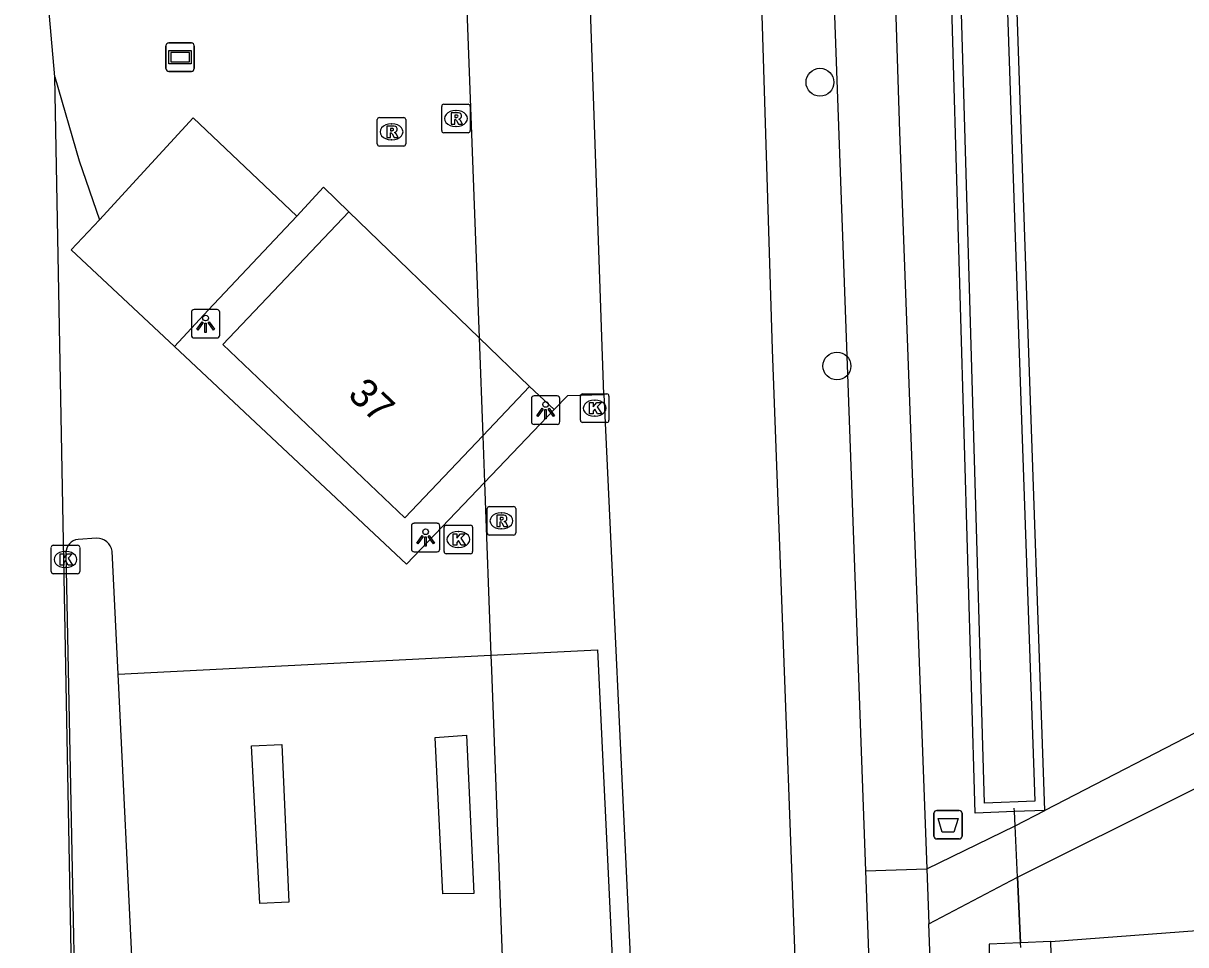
# Model space of a CAD drawing. Extents: x 162515 to 163909, y 388494 to 389773.
# Drawn here: x 162528.08 to 162568.87, y 388907.23 to 388939.56 of the extents above; entities that cross this region are included whole.
import ezdxf

# ---------------------------------------------------------------- set-up
doc = ezdxf.new("R2010")
doc.units = 0
for name, color, linetype in [('IMGEO_Afvalbak', 7, 'Continuous'), ('IMGEO_Berm_groen', 7, 'Continuous'), ('IMGEO_Boom', 7, 'Continuous'), ('IMGEO_Duiker', 7, 'Continuous'), ('IMGEO_Erf', 7, 'Continuous'), ('IMGEO_Grasland_overig', 7, 'Continuous'), ('IMGEO_Groenvoorziening', 7, 'Continuous'), ('IMGEO_Kolk', 7, 'Continuous'), ('IMGEO_Lichtpunt', 7, 'Continuous'), ('IMGEO_Loofbos', 7, 'Continuous'), ('IMGEO_Muur', 7, 'Continuous'), ('IMGEO_Pand', 7, 'Continuous'), ('IMGEO_Pand_nummerreeks', 7, 'Continuous'), ('IMGEO_Parkeervlak_open', 7, 'Continuous'), ('IMGEO_Reclamebord', 7, 'Continuous'), ('IMGEO_Rijbaan_lokaal_gesloten', 7, 'Continuous'), ('IMGEO_Rijbaan_lokaal_onverhard', 7, 'Continuous'), ('IMGEO_Rijbaan_lokaal_open', 7, 'Continuous'), ('IMGEO_Rijbaan_regionaal_gesloten', 7, 'Continuous'), ('IMGEO_Rioolput', 7, 'Continuous'), ('IMGEO_Voetpad_open', 7, 'Continuous'), ('IMGEO_Waterloop', 7, 'Continuous')]:
    doc.layers.add(name, color=color, linetype=linetype)

msp = doc.modelspace()

# ---------------------------------------------------------------- linework, layer by layer
at = {"layer": 'IMGEO_Afvalbak'}
for p, q in [((162560.036, 388911.045), (162560.036, 388911.845)), ((162560.036, 388911.845), (162560.036, 388911.045)), ((162560.136, 388911.945), (162560.926, 388911.945)), ((162560.926, 388911.945), (162560.136, 388911.945)), ((162561.026, 388911.845), (162561.026, 388911.045)), ((162561.026, 388911.045), (162561.026, 388911.845)), ((162560.926, 388910.945), (162560.136, 388910.945)), ((162560.136, 388910.945), (162560.926, 388910.945))]:
    msp.add_line(p, q, dxfattribs=at)
msp.add_lwpolyline([(162560.179, 388911.659), (162560.883, 388911.659), (162560.734, 388911.189), (162560.328, 388911.189), (162560.179, 388911.659)], dxfattribs=at)
for centre, start, end in [((162560.136, 388911.845), 90, 180), ((162560.136, 388911.845), 90, 180), ((162560.926, 388911.845), 0, 90), ((162560.926, 388911.845), 360, 90), ((162560.136, 388911.045), 180, 270), ((162560.136, 388911.045), 180, 270), ((162560.926, 388911.045), 270, 0), ((162560.926, 388911.045), 270, 0)]:
    msp.add_arc(centre, 0.1, start, end, dxfattribs=at)
at = {"layer": 'IMGEO_Berm_groen'}
msp.add_lwpolyline([(162563.923, 388911.946), (162562.861, 388911.906), (162561.484, 388911.855), (162559.805, 388969.627), (162558.753, 389000), (162555.964, 389080.524), (162557.523, 389080.69)], dxfattribs=at)
at = {"layer": 'IMGEO_Boom'}
for centre in [(162556.038, 388937.492), (162556.631, 388927.537)]:
    msp.add_circle(centre, 0.489, dxfattribs=at)
at = {"layer": 'IMGEO_Duiker'}
for points in [[(162543.608, 388941.114), (162543.637, 388940.341), (162544.076, 388928.528), (162544.204, 388925.086), (162544.265, 388923.449), (162544.49, 388917.392), (162544.51, 388916.869), (162544.884, 388906.812), (162544.893, 388906.576), (162545.214, 388897.949), (162545.319, 388895.129), (162545.332, 388894.768)], [(162563.083, 388907.137), (162563.075, 388907.302), (162562.968, 388909.608), (162562.884, 388911.41), (162562.861, 388911.906), (162562.853, 388912.022)]]:
    msp.add_lwpolyline(points, dxfattribs=at)
at = {"layer": 'IMGEO_Erf'}
msp.add_lwpolyline([(162563.923, 388911.946), (162563.311, 388929.674), (162561.923, 388970.136), (162560.632, 389000), (162557.523, 389080.69)], dxfattribs=at)
at = {"layer": 'IMGEO_Grasland_overig'}
for points in [[(162562.968, 388909.608), (162563.075, 388907.302)], [(162564.138, 388907.346), (162563.075, 388907.302)]]:
    msp.add_lwpolyline(points, dxfattribs=at)
at = {"layer": 'IMGEO_Groenvoorziening'}
msp.add_lwpolyline([(162563.075, 388907.302), (162561.978, 388907.257), (162562.125, 388898.48), (162562.164, 388896.116), (162562.928, 388869.681), (162566.625, 388758.14)], dxfattribs=at)
at = {"layer": 'IMGEO_Kolk'}
for p, q in [((162547.634, 388925.632), (162547.634, 388926.484)), ((162547.709, 388926.558), (162548.561, 388926.558)), ((162548.635, 388926.484), (162548.635, 388925.632)), ((162548.122, 388926.338), (162548.147, 388926.338)), ((162548.561, 388925.558), (162547.709, 388925.558)), ((162548.145, 388925.778), (162548.12, 388925.778)), ((162542.925, 388921.952), (162543.777, 388921.952)), ((162542.85, 388921.026), (162542.85, 388921.878)), ((162543.338, 388921.732), (162543.363, 388921.732)), ((162543.851, 388921.878), (162543.851, 388921.026)), ((162529.064, 388920.324), (162529.064, 388921.176)), ((162529.139, 388921.25), (162529.991, 388921.25)), ((162530.065, 388921.176), (162530.065, 388920.324)), ((162543.361, 388921.172), (162543.336, 388921.172)), ((162529.552, 388921.03), (162529.577, 388921.03)), ((162543.777, 388920.952), (162542.925, 388920.952)), ((162529.991, 388920.25), (162529.139, 388920.25)), ((162529.575, 388920.47), (162529.55, 388920.47))]:
    msp.add_line(p, q, dxfattribs=at)
for points in [[(162547.634, 388925.632), (162547.634, 388926.484)], [(162547.709, 388926.558), (162548.561, 388926.558)], [(162548.635, 388926.484), (162548.635, 388925.632)], [(162547.955, 388926.258), (162548.078, 388926.258), (162548.078, 388926.107), (162548.208, 388926.258), (162548.372, 388926.258), (162548.226, 388926.107), (162548.379, 388925.858), (162548.227, 388925.858), (162548.142, 388926.022), (162548.078, 388925.955), (162548.078, 388925.858), (162547.955, 388925.858), (162547.955, 388926.258)], [(162548.561, 388925.558), (162547.709, 388925.558)], [(162542.925, 388921.952), (162543.777, 388921.952)], [(162542.85, 388921.026), (162542.85, 388921.878)], [(162543.171, 388921.652), (162543.294, 388921.652), (162543.294, 388921.501), (162543.424, 388921.652), (162543.588, 388921.652), (162543.442, 388921.501), (162543.595, 388921.252), (162543.443, 388921.252), (162543.358, 388921.416), (162543.294, 388921.349), (162543.294, 388921.252), (162543.171, 388921.252), (162543.171, 388921.652)], [(162543.851, 388921.878), (162543.851, 388921.026)], [(162529.064, 388920.324), (162529.064, 388921.176)], [(162529.139, 388921.25), (162529.991, 388921.25)], [(162530.065, 388921.176), (162530.065, 388920.324)], [(162529.385, 388920.95), (162529.508, 388920.95), (162529.508, 388920.799), (162529.638, 388920.95), (162529.802, 388920.95), (162529.656, 388920.799), (162529.809, 388920.55), (162529.657, 388920.55), (162529.572, 388920.714), (162529.508, 388920.647), (162529.508, 388920.55), (162529.385, 388920.55), (162529.385, 388920.95)], [(162543.777, 388920.952), (162542.925, 388920.952)], [(162529.991, 388920.25), (162529.139, 388920.25)]]:
    msp.add_lwpolyline(points, dxfattribs=at)
for centre, start, end in [((162547.711, 388926.482), 91.552, 178.448), ((162547.711, 388926.482), 91.552, 178.448), ((162548.559, 388926.482), 1.552, 88.448), ((162548.559, 388926.482), 1.552, 88.448), ((162547.711, 388925.634), 181.552, 268.448), ((162547.711, 388925.634), 181.552, 268.448), ((162548.559, 388925.634), 271.552, 358.448), ((162548.559, 388925.634), 271.552, 358.448), ((162542.927, 388921.876), 91.552, 178.448), ((162542.927, 388921.876), 91.552, 178.448), ((162543.775, 388921.876), 1.552, 88.448), ((162543.775, 388921.876), 1.552, 88.448), ((162529.141, 388921.174), 91.552, 178.448), ((162529.141, 388921.174), 91.552, 178.448), ((162529.989, 388921.174), 1.552, 88.448), ((162529.989, 388921.174), 1.552, 88.448), ((162542.927, 388921.028), 181.552, 268.448), ((162542.927, 388921.028), 181.552, 268.448), ((162543.775, 388921.028), 271.552, 358.448), ((162543.775, 388921.028), 271.552, 358.448), ((162529.141, 388920.326), 181.552, 268.448), ((162529.141, 388920.326), 181.552, 268.448), ((162529.989, 388920.326), 271.552, 358.448), ((162529.989, 388920.326), 271.552, 358.448)]:
    msp.add_arc(centre, 0.0765, start, end, dxfattribs=at)
for centre, major_axis, ratio, start_param, end_param in [((162548.121, 388926.058), (-0.387, 0.002), 0.722429, 4.712389, 7.853982), ((162548.146, 388926.058), (-0.39, 0.002), 0.717154, 1.570796, 4.712389), ((162543.337, 388921.452), (-0.387, 0.002), 0.722429, 4.712389, 7.853982), ((162543.362, 388921.452), (-0.39, 0.002), 0.717154, 1.570796, 4.712389), ((162529.551, 388920.75), (-0.387, 0.002), 0.722429, 4.712389, 7.853982), ((162529.576, 388920.75), (-0.39, 0.002), 0.717154, 1.570796, 4.712389)]:
    msp.add_ellipse(centre, major_axis=major_axis, ratio=ratio, start_param=start_param, end_param=end_param, dxfattribs=at)
at = {"layer": 'IMGEO_Lichtpunt'}
for p, q in [((162533.983, 388929.423), (162533.983, 388928.616)), ((162533.983, 388929.423), (162533.983, 388928.616)), ((162534.885, 388929.518), (162534.077, 388929.518)), ((162534.885, 388929.518), (162534.077, 388929.518)), ((162534.979, 388928.616), (162534.979, 388929.423)), ((162534.979, 388928.616), (162534.979, 388929.423)), ((162534.077, 388928.522), (162534.885, 388928.522)), ((162534.077, 388928.522), (162534.885, 388928.522)), ((162545.913, 388926.392), (162545.913, 388925.585)), ((162545.913, 388926.392), (162545.913, 388925.585)), ((162546.815, 388926.487), (162546.007, 388926.487)), ((162546.815, 388926.487), (162546.007, 388926.487)), ((162546.909, 388925.585), (162546.909, 388926.392)), ((162546.909, 388925.585), (162546.909, 388926.392)), ((162546.007, 388925.491), (162546.815, 388925.491)), ((162546.007, 388925.491), (162546.815, 388925.491)), ((162541.703, 388921.923), (162541.703, 388921.116)), ((162541.703, 388921.923), (162541.703, 388921.116)), ((162542.605, 388922.018), (162541.797, 388922.018)), ((162542.605, 388922.018), (162541.797, 388922.018)), ((162542.699, 388921.116), (162542.699, 388921.923)), ((162542.699, 388921.116), (162542.699, 388921.923)), ((162541.797, 388921.022), (162542.605, 388921.022)), ((162541.797, 388921.022), (162542.605, 388921.022))]:
    msp.add_line(p, q, dxfattribs=at)
for points in [[(162534.357, 388929.087), (162534.396, 388929.059), (162534.208, 388928.797), (162534.17, 388928.824), (162534.357, 388929.087)], [(162534.459, 388929.039), (162534.506, 388929.039), (162534.506, 388928.717), (162534.459, 388928.717), (162534.459, 388929.039)], [(162534.569, 388929.059), (162534.607, 388929.086), (162534.794, 388928.824), (162534.755, 388928.796), (162534.569, 388929.059)], [(162546.287, 388926.056), (162546.326, 388926.028), (162546.138, 388925.766), (162546.1, 388925.793), (162546.287, 388926.056)], [(162546.389, 388926.008), (162546.436, 388926.008), (162546.436, 388925.686), (162546.389, 388925.686), (162546.389, 388926.008)], [(162546.499, 388926.028), (162546.537, 388926.055), (162546.724, 388925.793), (162546.685, 388925.765), (162546.499, 388926.028)], [(162542.077, 388921.587), (162542.116, 388921.559), (162541.928, 388921.297), (162541.89, 388921.324), (162542.077, 388921.587)], [(162542.179, 388921.539), (162542.226, 388921.539), (162542.226, 388921.217), (162542.179, 388921.217), (162542.179, 388921.539)], [(162542.289, 388921.559), (162542.327, 388921.586), (162542.514, 388921.324), (162542.475, 388921.296), (162542.289, 388921.559)]]:
    msp.add_lwpolyline(points, dxfattribs=at)
for centre in [(162534.482, 388929.221), (162546.412, 388926.19), (162542.202, 388921.721)]:
    msp.add_circle(centre, 0.0994, dxfattribs=at)
for centre, start, end in [((162534.077, 388929.423), 90, 180), ((162534.077, 388929.423), 90, 180), ((162534.885, 388929.423), 0, 90), ((162534.885, 388929.423), 0, 90), ((162534.077, 388928.616), 180, 270), ((162534.077, 388928.616), 180, 270), ((162534.885, 388928.616), 270, 0), ((162534.885, 388928.616), 270, 360), ((162546.007, 388926.392), 90, 180), ((162546.007, 388926.392), 90, 180), ((162546.815, 388926.392), 0, 90), ((162546.815, 388926.392), 0, 90), ((162546.007, 388925.585), 180, 270), ((162546.007, 388925.585), 180, 270), ((162546.815, 388925.585), 270, 0), ((162546.815, 388925.585), 270, 360), ((162541.797, 388921.923), 90, 180), ((162541.797, 388921.923), 90, 180), ((162542.605, 388921.923), 0, 90), ((162542.605, 388921.923), 0, 90), ((162541.797, 388921.116), 180, 270), ((162541.797, 388921.116), 180, 270), ((162542.605, 388921.116), 270, 0), ((162542.605, 388921.116), 270, 360)]:
    msp.add_arc(centre, 0.0946, start, end, dxfattribs=at)
at = {"layer": 'IMGEO_Loofbos'}
for points in [[(162564.138, 388907.346), (162579.188, 388908.487), (162582.543, 388908.673), (162586.016, 388909.208), (162589.2, 388911.235), (162591.276, 388913.312), (162595.016, 388915.557), (162602.021, 388918.902), (162607.311, 388919.836), (162614.857, 388920.843), (162623.805, 388920.843)], [(162564.26, 388902.984), (162564.138, 388907.346)]]:
    msp.add_lwpolyline(points, dxfattribs=at)
at = {"layer": 'IMGEO_Muur'}
for points in [[(162542.807, 388909.02), (162542.537, 388914.506), (162543.64, 388914.581), (162543.898, 388909.031), (162542.807, 388909.02)], [(162536.38, 388908.687), (162536.087, 388914.209), (162537.152, 388914.255), (162537.408, 388908.733), (162536.38, 388908.687)]]:
    msp.add_lwpolyline(points, dxfattribs=at)
at = {"layer": 'IMGEO_Pand'}
for points in [[(162539.511, 388932.95), (162535.084, 388928.294), (162541.469, 388922.21), (162544.204, 388925.086), (162545.846, 388926.813)], [(162539.511, 388932.95), (162544.076, 388928.528), (162545.846, 388926.813)]]:
    msp.add_lwpolyline(points, dxfattribs=at)
at = {"layer": 'IMGEO_Parkeervlak_open'}
msp.add_lwpolyline([(162530.757, 388932.669), (162532.187, 388934.223), (162534.049, 388936.247), (162537.685, 388932.796)], dxfattribs=at)
at = {"layer": 'IMGEO_Reclamebord'}
for p, q in [((162533.092, 388937.972), (162533.092, 388938.772)), ((162533.092, 388938.772), (162533.092, 388937.972)), ((162533.192, 388938.872), (162533.982, 388938.872)), ((162533.982, 388938.872), (162533.192, 388938.872)), ((162534.082, 388938.772), (162534.082, 388937.972)), ((162534.082, 388937.972), (162534.082, 388938.772)), ((162533.982, 388937.872), (162533.192, 388937.872)), ((162533.192, 388937.872), (162533.982, 388937.872))]:
    msp.add_line(p, q, dxfattribs=at)
for points in [[(162533.193, 388938.604), (162533.981, 388938.604), (162533.981, 388938.14), (162533.193, 388938.14), (162533.193, 388938.604)], [(162533.258, 388938.539), (162533.258, 388938.205), (162533.916, 388938.205), (162533.916, 388938.539), (162533.258, 388938.539)]]:
    msp.add_lwpolyline(points, dxfattribs=at)
for centre, start, end in [((162533.192, 388938.772), 90, 180), ((162533.192, 388938.772), 90, 180), ((162533.982, 388938.772), 0, 90), ((162533.982, 388938.772), 360, 90), ((162533.192, 388937.972), 180, 270), ((162533.192, 388937.972), 180, 270), ((162533.982, 388937.972), 270, 0), ((162533.982, 388937.972), 270, 0)]:
    msp.add_arc(centre, 0.1, start, end, dxfattribs=at)
at = {"layer": 'IMGEO_Rijbaan_lokaal_gesloten'}
for points in [[(162549.626, 389079.22), (162550.263, 389055.871), (162552.144, 389000), (162554.359, 388928.112), (162555.469, 388898.319), (162558.904, 388806.077)], [(162548.457, 388926.534), (162547.973, 388940.397)], [(162548.457, 388926.534), (162549.378, 388906.825), (162549.343, 388893.807)], [(162531.416, 388916.726), (162544.49, 388917.392), (162548.231, 388917.583), (162548.747, 388906.784), (162544.893, 388906.576), (162531.94, 388905.879)], [(162531.94, 388905.879), (162531.416, 388916.726)]]:
    msp.add_lwpolyline(points, dxfattribs=at)
at = {"layer": 'IMGEO_Rijbaan_lokaal_onverhard'}
for points in [[(162562.968, 388909.608), (162574.616, 388915.42), (162585.281, 388919.419), (162594.576, 388923.478), (162598.939, 388924.91), (162600.985, 388925.217), (162617.1, 388925.781), (162621.182, 388924.915), (162624.728, 388924.763)], [(162569.898, 388915.03), (162563.923, 388911.946)], [(162559.784, 388909.9), (162562.884, 388911.41), (162563.923, 388911.946)], [(162559.784, 388909.9), (162559.856, 388907.965)], [(162559.856, 388907.965), (162562.968, 388909.608)]]:
    msp.add_lwpolyline(points, dxfattribs=at)
at = {"layer": 'IMGEO_Rijbaan_lokaal_open'}
for points in [[(162529.193, 388937.678), (162530.043, 388934.731), (162530.757, 388932.669)], [(162533.388, 388928.227), (162529.768, 388931.618), (162530.757, 388932.669)], [(162546.717, 388926.017), (162544.265, 388923.449), (162541.53, 388920.585), (162533.388, 388928.227)], [(162546.717, 388926.017), (162547.197, 388926.503), (162548.457, 388926.534)], [(162530.659, 388921.497), (162530.009, 388921.456)], [(162529.574, 388920.976), (162530.124, 388893.52)], [(162531.416, 388916.726), (162531.202, 388921.043)]]:
    msp.add_lwpolyline(points, dxfattribs=at)
for centre, radius, start, end in [((162530.664, 388920.951), 0.546, 9.6812, 90.521), ((162530.078, 388920.957), 0.504, 97.8158, 177.8153)]:
    msp.add_arc(centre, radius, start, end, dxfattribs=at)
at = {"layer": 'IMGEO_Rijbaan_regionaal_gesloten'}
for points in [[(162529.193, 388937.678), (162528.839, 388941.677), (162528.689, 388944.843), (162528.341, 388968.251), (162528.084, 389000), (162528.308, 389035.787), (162529.495, 389069.241), (162530.272, 389081.426)], [(162533.787, 388868.298), (162530.485, 388868.12), (162529.193, 388937.678)]]:
    msp.add_lwpolyline(points, dxfattribs=at)
at = {"layer": 'IMGEO_Rioolput'}
for p, q in [((162542.765, 388935.794), (162542.765, 388936.646)), ((162542.84, 388936.72), (162543.692, 388936.72)), ((162543.766, 388936.646), (162543.766, 388935.794)), ((162540.506, 388935.328), (162540.506, 388936.18)), ((162540.581, 388936.254), (162541.433, 388936.254)), ((162541.507, 388936.18), (162541.507, 388935.328)), ((162543.253, 388936.5), (162543.278, 388936.5)), ((162540.994, 388936.034), (162541.019, 388936.034)), ((162543.276, 388935.94), (162543.251, 388935.94)), ((162541.017, 388935.474), (162540.992, 388935.474)), ((162543.692, 388935.72), (162542.84, 388935.72)), ((162541.433, 388935.254), (162540.581, 388935.254)), ((162544.36, 388921.681), (162544.36, 388922.533)), ((162544.435, 388922.607), (162545.287, 388922.607)), ((162544.848, 388922.387), (162544.873, 388922.387)), ((162545.361, 388922.533), (162545.361, 388921.681)), ((162545.287, 388921.607), (162544.435, 388921.607)), ((162544.871, 388921.827), (162544.846, 388921.827))]:
    msp.add_line(p, q, dxfattribs=at)
for points in [[(162542.765, 388935.794), (162542.765, 388936.646)], [(162542.84, 388936.72), (162543.692, 388936.72)], [(162543.766, 388936.646), (162543.766, 388935.794)], [(162540.506, 388935.328), (162540.506, 388936.18)], [(162540.581, 388936.254), (162541.433, 388936.254)], [(162541.507, 388936.18), (162541.507, 388935.328)], [(162543.354, 388936.418), (162543.102, 388936.42), (162543.102, 388936.02)], [(162543.102, 388936.02), (162543.226, 388936.02), (162543.226, 388936.182), (162543.237, 388936.182)], [(162543.28, 388936.339), (162543.226, 388936.339), (162543.226, 388936.258)], [(162543.226, 388936.258), (162543.278, 388936.258)], [(162541.095, 388935.952), (162540.843, 388935.954), (162540.843, 388935.554)], [(162541.021, 388935.873), (162540.967, 388935.873), (162540.967, 388935.792)], [(162540.967, 388935.792), (162541.019, 388935.792)], [(162543.284, 388936.153), (162543.355, 388936.02), (162543.495, 388936.02), (162543.43, 388936.146)], [(162540.843, 388935.554), (162540.967, 388935.554), (162540.967, 388935.716), (162540.978, 388935.716)], [(162541.025, 388935.687), (162541.096, 388935.554), (162541.236, 388935.554), (162541.171, 388935.68)], [(162543.692, 388935.72), (162542.84, 388935.72)], [(162541.433, 388935.254), (162540.581, 388935.254)], [(162544.36, 388921.681), (162544.36, 388922.533)], [(162544.435, 388922.607), (162545.287, 388922.607)], [(162544.949, 388922.305), (162544.697, 388922.307), (162544.697, 388921.907)], [(162545.361, 388922.533), (162545.361, 388921.681)], [(162544.697, 388921.907), (162544.821, 388921.907), (162544.821, 388922.069), (162544.832, 388922.069)], [(162544.875, 388922.226), (162544.821, 388922.226), (162544.821, 388922.145)], [(162544.821, 388922.145), (162544.873, 388922.145)], [(162544.879, 388922.04), (162544.95, 388921.907), (162545.09, 388921.907), (162545.025, 388922.033)], [(162545.287, 388921.607), (162544.435, 388921.607)]]:
    msp.add_lwpolyline(points, dxfattribs=at)
for centre, radius, start, end in [((162542.842, 388936.644), 0.0765, 91.552, 178.448), ((162542.842, 388936.644), 0.0765, 91.552, 178.448), ((162543.69, 388936.644), 0.0765, 1.552, 88.448), ((162543.69, 388936.644), 0.0765, 1.552, 88.448), ((162540.583, 388936.178), 0.0765, 91.552, 178.448), ((162540.583, 388936.178), 0.0765, 91.552, 178.448), ((162541.431, 388936.178), 0.0765, 1.552, 88.448), ((162541.431, 388936.178), 0.0765, 1.552, 88.448), ((162543.236, 388936.129), 0.0533, 26.0293, 88.6989), ((162543.262, 388936.447), 0.19, 274.7715, 282.9687), ((162543.286, 388936.243), 0.0964, 77.0061, 93.1865), ((162543.3, 388936.3), 0.0378, 276.6634, 79.6772), ((162543.353, 388936.308), 0.109, 350.3612, 89.416), ((162543.351, 388936.308), 0.112, 277.5842, 350.9817), ((162543.335, 388936.093), 0.108, 29.5134, 73.7905), ((162541.003, 388935.981), 0.19, 274.7715, 282.9687), ((162541.027, 388935.777), 0.0964, 77.0061, 93.1865), ((162541.041, 388935.834), 0.0378, 276.6634, 79.6772), ((162541.094, 388935.842), 0.109, 350.3612, 89.416), ((162541.092, 388935.842), 0.112, 277.5842, 350.9817), ((162542.842, 388935.796), 0.0765, 181.552, 268.448), ((162542.842, 388935.796), 0.0765, 181.552, 268.448), ((162543.69, 388935.796), 0.0765, 271.552, 358.448), ((162543.69, 388935.796), 0.0765, 271.552, 358.448), ((162540.977, 388935.663), 0.0533, 26.0293, 88.6989), ((162541.076, 388935.627), 0.108, 29.5134, 73.7905), ((162540.583, 388935.33), 0.0765, 181.552, 268.448), ((162540.583, 388935.33), 0.0765, 181.552, 268.448), ((162541.431, 388935.33), 0.0765, 271.552, 358.448), ((162541.431, 388935.33), 0.0765, 271.552, 358.448), ((162544.437, 388922.531), 0.0765, 91.552, 178.448), ((162544.437, 388922.531), 0.0765, 91.552, 178.448), ((162544.948, 388922.195), 0.109, 350.3612, 89.416), ((162545.285, 388922.531), 0.0765, 1.552, 88.448), ((162545.285, 388922.531), 0.0765, 1.552, 88.448), ((162544.831, 388922.016), 0.0533, 26.0293, 88.6989), ((162544.857, 388922.334), 0.19, 274.7715, 282.9687), ((162544.881, 388922.13), 0.0964, 77.0061, 93.1865), ((162544.895, 388922.187), 0.0378, 276.6634, 79.6772), ((162544.946, 388922.195), 0.112, 277.5842, 350.9817), ((162544.93, 388921.98), 0.108, 29.5134, 73.7905), ((162544.437, 388921.683), 0.0765, 181.552, 268.448), ((162544.437, 388921.683), 0.0765, 181.552, 268.448), ((162545.285, 388921.683), 0.0765, 271.552, 358.448), ((162545.285, 388921.683), 0.0765, 271.552, 358.448)]:
    msp.add_arc(centre, radius, start, end, dxfattribs=at)
for centre, major_axis, ratio, start_param, end_param in [((162543.252, 388936.22), (-0.387, 0.002), 0.722429, 4.712389, 7.853982), ((162543.277, 388936.22), (-0.39, 0.002), 0.717154, 1.570796, 4.712389), ((162540.993, 388935.754), (-0.387, 0.002), 0.722429, 4.712389, 7.853982), ((162541.018, 388935.754), (-0.39, 0.002), 0.717154, 1.570796, 4.712389), ((162544.847, 388922.107), (-0.387, 0.002), 0.722429, 4.712389, 7.853982), ((162544.872, 388922.107), (-0.39, 0.002), 0.717154, 1.570796, 4.712389)]:
    msp.add_ellipse(centre, major_axis=major_axis, ratio=ratio, start_param=start_param, end_param=end_param, dxfattribs=at)
at = {"layer": 'IMGEO_Voetpad_open'}
for points in [[(162552.027, 389082.807), (162554.571, 389000), (162556.233, 388948.545), (162557.64, 388909.822)], [(162555.482, 389035.321), (162556.784, 389000), (162558.826, 388935.752), (162559.784, 388909.9)], [(162537.685, 388932.796), (162538.613, 388933.806), (162539.511, 388932.95)], [(162537.685, 388932.796), (162534.577, 388929.497), (162533.388, 388928.227)], [(162545.846, 388926.813), (162546.717, 388926.017)], [(162557.64, 388909.822), (162559.784, 388909.9)], [(162557.64, 388909.822), (162558.056, 388898.382), (162561.333, 388808.202)], [(162563.548, 388808.329), (162560.209, 388898.434), (162559.856, 388907.965)]]:
    msp.add_lwpolyline(points, dxfattribs=at)
at = {"layer": 'IMGEO_Waterloop'}
msp.add_lwpolyline([(162557.199, 389080.315), (162560.294, 388999.986), (162561.585, 388970.123), (162562.973, 388929.662), (162563.573, 388912.272), (162561.813, 388912.206), (162560.143, 388969.638), (162559.091, 389000.012), (162556.313, 389080.221), (162557.199, 389080.315)], dxfattribs=at)

# ---------------------------------------------------------------- texts
at = {"layer": 'IMGEO_Pand_nummerreeks'}
msp.add_text('37', height=1, rotation=316.473, dxfattribs=at).set_placement((162539.431, 388926.484))

doc.saveas('drawing.dxf')
